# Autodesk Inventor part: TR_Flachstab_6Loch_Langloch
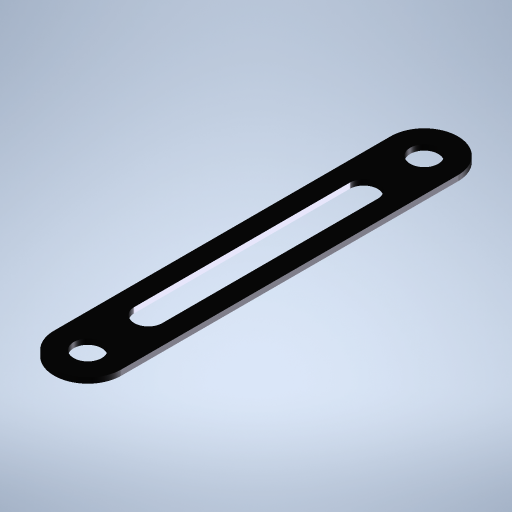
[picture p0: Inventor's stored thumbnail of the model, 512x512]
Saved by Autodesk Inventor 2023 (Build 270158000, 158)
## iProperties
Created: 2023-11
Part Number: TR_Flachstab_6Loch_Langloch
Material: Edelstahl
Document SubType Name: Modeling
Designer: Admin
Density: 8 g/cm^3
Appearance: Halbpoliert
Author: Admin
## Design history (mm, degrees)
sketch "Skizze1"
  geometry: L1 (0, 25)-(0, -25); L2 (-5, 25)-(-5, -25); L3 (5, -25)-(5, 25); A1 r 5 centre (0, 25) between (5, 25) and (-5, 25); A2 r 5 centre (0, -25) between (-5, -25) and (5, -25); 3 further points
  constraints: 8 end point, 4 point on circle, 4 tangent, 2 centre point, 2 midpoint, 1 horizontal alignment, 1 parallel, 1 vertical, 1 vertical alignment
  dimensions: "d0" = 50 distance of L1.start L1.end (computed from Loch, Einheitsmaß); "d1" = 5 radius of A1 (= 0.5 x Einheitsmaß)
extrude "Extrusion1" new body sketch "Skizze1" distance "d5" = 0.8 (= Dicke); taper "d6" = 0 deg
sketch "Skizze2"
  geometry: L1 (0, 16)-(0, -16); L2 (-2.075, 16)-(-2.075, -16); L3 (2.075, -16)-(2.075, 16); C1 r 2.075 at (0, 25); C2 r 2.075 at (0, -25); A1 r 5 centre (0, 25) between (5, 25) and (-5, 25) reference; A2 r 5 centre (0, -25) between (-5, -25) and (5, -25) reference; A3 r 2.075 centre (0, 16) between (2.075, 16) and (-2.075, 16); A4 r 2.075 centre (0, -16) between (-2.075, -16) and (2.075, -16); 3 further points
  constraints: 8 end point, 4 centre point, 4 point on circle, 4 tangent, 3 midpoint, 2 coincident, 1 equal radius, 1 horizontal alignment, 1 parallel, 1 vertical
  dimensions: "d7" = 4.15 diameter of C1 (= 2 x Radius); "d13" = 4.15 diameter of C2 (= 2 x Radius); "d14" = 32 distance of L1.start L1.end
extrude "Extrusion2" cut sketch "Skizze2" stored distance "d8" = 10; taper "d9" = 0 deg
node "Volumenkörper1"
other parameters: "Radius" = 2.075 [user parameter; used in 2 equation terms], "Fasen" = 0.5 [user parameter], "Dicke" = 0.8 [user parameter; used in 1 equation term]
